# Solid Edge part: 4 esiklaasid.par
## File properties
Author: Henri
Template: Normal.par
Last saved by: Henri
Revision: 18
Application: Solid Edge
Accuracy: 0,990
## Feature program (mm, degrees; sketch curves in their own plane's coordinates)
sketch for "unnamed Protrusion 1" #1 plane through (178.0953, -250, 44.6428) normal (0.514496, 0, 0.857493) x-axis (0, 1, 0)
  line (-205, 61.7735) -> (-15, 61.7735)
  arc centre (-15, 51.7735) radius 10 from (-15, 61.7735) to (-5, 51.7735) cw
  line (-5, 51.7735) -> (-5, -51.7701)
  arc centre (-15, -51.7701) radius 10 from (-15, -61.7701) to (-5, -51.7701) ccw
  line (-15, -61.7701) -> (-205, -61.7701)
  arc centre (-205, -51.7701) radius 10 from (-215, -51.7701) to (-205, -61.7701) ccw
  line (-215, -51.7701) -> (-215, 51.7735)
  arc centre (-205, 51.7735) radius 10 from (-215, 51.7735) to (-205, 61.7735) cw
sketch for "unnamed Protrusion 1" #2 plane through (178.0953, -250, 44.6428) normal (0.514496, 0, 0.857493) x-axis (0, 1, 0)
  line (15, 61.7735) -> (205.778, 61.7735)
  arc centre (205.778, 52.5515) radius 9.222 from (215, 52.5515) to (205.778, 61.7735) ccw
  line (215, 52.5515) -> (215, -52.5481)
  arc centre (205.778, -52.5481) radius 9.222 from (205.778, -61.7701) to (215, -52.5481) ccw
  line (205.778, -61.7701) -> (15, -61.7701)
  arc centre (15, -51.7701) radius 10 from (5, -51.7701) to (15, -61.7701) ccw
  line (5, -51.7701) -> (5, 51.7735)
  arc centre (15, 51.7735) radius 10 from (5, 51.7735) to (15, 61.7735) cw
extrude "unnamed Protrusion 1" add finite 5 along -normal
sketch for "ExtrudedProtrusion_6" #1 plane through (178.0938, -360, 44.6437) normal (0.514496, 0, 0.857493) x-axis (0, 1, 0)
  line (-95, 64.2718) -> (95, 64.2718)
  arc centre (95, 51.7718) radius 12.5 from (95, 64.2718) to (107.5, 51.7718) cw
  line (107.5, 51.7718) -> (107.5, -51.7718)
  arc centre (95, -51.7718) radius 12.5 from (95, -64.2718) to (107.5, -51.7718) ccw
  line (95, -64.2718) -> (-95, -64.2718)
  arc centre (-95, -51.7718) radius 12.5 from (-107.5, -51.7718) to (-95, -64.2718) ccw
  line (-107.5, -51.7718) -> (-107.5, 51.7718)
  arc centre (-95, 51.7718) radius 12.5 from (-107.5, 51.7718) to (-95, 64.2718) cw
sketch for "ExtrudedProtrusion_6" #2 plane through (178.0938, -360, 44.6437) normal (0.514496, 0, 0.857493) x-axis (0, 1, 0)
  line (-95, 59.2718) -> (95, 59.2718)
  arc centre (95, 51.7718) radius 7.5 from (95, 59.2718) to (102.5, 51.7718) cw
  line (102.5, 51.7718) -> (102.5, -51.7718)
  arc centre (95, -51.7718) radius 7.5 from (95, -59.2718) to (102.5, -51.7718) ccw
  line (95, -59.2718) -> (-95, -59.2718)
  arc centre (-95, -51.7718) radius 7.5 from (-102.5, -51.7718) to (-95, -59.2718) ccw
  line (-102.5, -51.7718) -> (-102.5, 51.7718)
  arc centre (-95, 51.7718) radius 7.5 from (-102.5, 51.7718) to (-95, 59.2718) cw
sketch for "ExtrudedProtrusion_6" #3 plane through (178.0938, -360, 44.6437) normal (0.514496, 0, 0.857493) x-axis (0, 1, 0)
  line (125, 64.2718) -> (315.778, 64.2718)
  arc centre (315.778, 52.5498) radius 11.722 from (327.5, 52.5498) to (315.778, 64.2718) ccw
  line (327.5, 52.5498) -> (327.5, -52.5498)
  arc centre (315.778, -52.5498) radius 11.722 from (315.778, -64.2718) to (327.5, -52.5498) ccw
  line (315.778, -64.2718) -> (125, -64.2718)
  arc centre (125, -51.7718) radius 12.5 from (112.5, -51.7718) to (125, -64.2718) ccw
  line (112.5, -51.7718) -> (112.5, 51.7718)
  arc centre (125, 51.7718) radius 12.5 from (112.5, 51.7718) to (125, 64.2718) cw
sketch for "ExtrudedProtrusion_6" #4 plane through (178.0938, -360, 44.6437) normal (0.514496, 0, 0.857493) x-axis (0, 1, 0)
  line (125, 59.2718) -> (315.778, 59.2718)
  arc centre (315.778, 52.5498) radius 6.722 from (322.5, 52.5498) to (315.778, 59.2718) ccw
  line (322.5, 52.5498) -> (322.5, -52.5498)
  arc centre (315.778, -52.5498) radius 6.722 from (315.778, -59.2718) to (322.5, -52.5498) ccw
  line (315.778, -59.2718) -> (125, -59.2718)
  arc centre (125, -51.7718) radius 7.5 from (117.5, -51.7718) to (125, -59.2718) ccw
  line (117.5, -51.7718) -> (117.5, 51.7718)
  arc centre (125, 51.7718) radius 7.5 from (117.5, 51.7718) to (125, 59.2718) cw
extrude "ExtrudedProtrusion_6" add finite 2.5 along +normal
fillet "Round_20" radius 1
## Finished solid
Body 1: solid body, 88 faces, 208 edges, 128 vertices, 2 separate solids.
  Faces by surface: cylinder 40, plane 32, torus 16
  Edges by curve: line 112, circle 96
Bounding box of the edges (mm; curved faces can reach further): 111.568 x 435.000 x 70.908, from (122.5524, -467.5, 8.5749) to (234.1207, -32.5, 79.4831).
Cylindrical faces by radius (mm): R1 x16, R6.722 x2, R7.5 x6, R9.222 x2, R10 x6, R11.722 x2, R12.5 x6
Toroidal faces (ring radius, tube radius in mm): R7.722 r1 x2, R8.5 r1 x6, R10.722 r1 x2, R11.5 r1 x6
Planar faces by outward normal: +y 6, -y 6, oblique 20
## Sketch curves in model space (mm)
arc centre (133.6998, -265, 71.2801) radius 12.5 from (122.9811, -265, 77.7113) through (126.3442, -255.9078, 75.6935) to (133.6998, -252.5, 71.2801)
line (133.6998, -252.5, 71.2801) -> (222.4877, -252.5, 18.0074)
arc centre (222.4877, -265, 18.0074) radius 12.5 from (233.2064, -265, 11.5762) through (229.8433, -255.9078, 13.594) to (222.4877, -252.5, 18.0074)
line (233.2064, -265, 11.5762) -> (233.2064, -455, 11.5762)
arc centre (222.4877, -455, 18.0074) radius 12.5 from (222.4877, -467.5, 18.0074) through (230.2842, -463.578, 13.3295) to (233.2064, -455, 11.5762)
line (222.4877, -467.5, 18.0074) -> (133.6998, -467.5, 71.2801)
arc centre (133.6998, -455, 71.2801) radius 12.5 from (133.6998, -467.5, 71.2801) through (125.9033, -463.578, 75.958) to (122.9811, -455, 77.7113)
line (122.9811, -455, 77.7113) -> (122.9811, -265, 77.7113)
arc centre (133.6998, -265, 71.2801) radius 7.5 from (127.2686, -265, 75.1388) through (129.2865, -259.5447, 73.9281) to (133.6998, -257.5, 71.2801)
line (133.6998, -257.5, 71.2801) -> (222.4877, -257.5, 18.0074)
arc centre (222.4877, -265, 18.0074) radius 7.5 from (228.9189, -265, 14.1486) through (226.9011, -259.5447, 15.3593) to (222.4877, -257.5, 18.0074)
line (228.9189, -265, 14.1486) -> (228.9189, -455, 14.1486)
arc centre (222.4877, -455, 18.0074) radius 7.5 from (222.4877, -462.5, 18.0074) through (227.1656, -460.1468, 15.2006) to (228.9189, -455, 14.1486)
line (222.4877, -462.5, 18.0074) -> (133.6998, -462.5, 71.2801)
arc centre (133.6998, -455, 71.2801) radius 7.5 from (133.6998, -462.5, 71.2801) through (129.0219, -460.1468, 74.0868) to (127.2686, -455, 75.1388)
line (127.2686, -455, 75.1388) -> (127.2686, -265, 75.1388)
arc centre (133.6998, -235, 71.2801) radius 12.5 from (133.6998, -247.5, 71.2801) through (125.9033, -243.578, 75.958) to (122.9811, -235, 77.7113)
line (122.9811, -235, 77.7113) -> (122.9811, -44.222, 77.7113)
arc centre (133.0327, -44.222, 71.6804) radius 11.722 from (133.0327, -32.5, 71.6804) through (125.7215, -36.1779, 76.0671) to (122.9811, -44.222, 77.7113)
line (133.0327, -32.5, 71.6804) -> (223.1549, -32.5, 17.6071)
arc centre (223.1549, -44.222, 17.6071) radius 11.722 from (233.2064, -44.222, 11.5762) through (230.0527, -35.6957, 13.4684) to (223.1549, -32.5, 17.6071)
line (233.2064, -44.222, 11.5762) -> (233.2064, -235, 11.5762)
arc centre (222.4877, -235, 18.0074) radius 12.5 from (222.4877, -247.5, 18.0074) through (230.2842, -243.578, 13.3295) to (233.2064, -235, 11.5762)
line (222.4877, -247.5, 18.0074) -> (133.6998, -247.5, 71.2801)
arc centre (133.0327, -44.222, 71.6804) radius 6.722 from (133.0327, -37.5, 71.6804) through (128.84, -39.6091, 74.196) to (127.2686, -44.222, 75.1388)
line (133.0327, -37.5, 71.6804) -> (223.1549, -37.5, 17.6071)
arc centre (223.1549, -44.222, 17.6071) radius 6.722 from (228.9189, -44.222, 14.1486) through (227.1104, -39.3326, 15.2337) to (223.1549, -37.5, 17.6071)
line (228.9189, -44.222, 14.1486) -> (228.9189, -235, 14.1486)
arc centre (222.4877, -235, 18.0074) radius 7.5 from (222.4877, -242.5, 18.0074) through (227.1656, -240.1468, 15.2006) to (228.9189, -235, 14.1486)
line (222.4877, -242.5, 18.0074) -> (133.6998, -242.5, 71.2801)
arc centre (133.6998, -235, 71.2801) radius 7.5 from (133.6998, -242.5, 71.2801) through (129.0219, -240.1468, 74.0868) to (127.2686, -235, 75.1388)
line (127.2686, -235, 75.1388) -> (127.2686, -44.222, 75.1388)
arc centre (133.0327, -44.222, 71.6804) radius 9.222 from (133.0327, -35, 71.6804) through (127.2808, -37.8935, 75.1315) to (125.1249, -44.222, 76.4251)
line (133.0327, -35, 71.6804) -> (223.1549, -35, 17.6071)
arc centre (223.1549, -44.222, 17.6071) radius 9.222 from (231.0627, -44.222, 12.8624) through (228.5815, -37.5142, 14.3511) to (223.1549, -35, 17.6071)
line (231.0627, -44.222, 12.8624) -> (231.0627, -235, 12.8624)
arc centre (222.4877, -235, 18.0074) radius 10 from (222.4877, -245, 18.0074) through (228.7249, -241.8624, 14.265) to (231.0627, -235, 12.8624)
line (222.4877, -245, 18.0074) -> (133.6998, -245, 71.2801)
arc centre (133.6998, -235, 71.2801) radius 10 from (133.6998, -245, 71.2801) through (127.4626, -241.8624, 75.0224) to (125.1249, -235, 76.4251)
line (125.1249, -235, 76.4251) -> (125.1249, -44.222, 76.4251)
arc centre (133.6998, -265, 71.2801) radius 10 from (125.1249, -265, 76.4251) through (127.8153, -257.7263, 74.8108) to (133.6998, -255, 71.2801)
line (133.6998, -255, 71.2801) -> (222.4877, -255, 18.0074)
arc centre (222.4877, -265, 18.0074) radius 10 from (231.0627, -265, 12.8624) through (228.3722, -257.7263, 14.4767) to (222.4877, -255, 18.0074)
line (231.0627, -265, 12.8624) -> (231.0627, -455, 12.8624)
arc centre (222.4877, -455, 18.0074) radius 10 from (222.4877, -465, 18.0074) through (228.7249, -461.8624, 14.265) to (231.0627, -455, 12.8624)
line (222.4877, -465, 18.0074) -> (133.6998, -465, 71.2801)
arc centre (133.6998, -455, 71.2801) radius 10 from (133.6998, -465, 71.2801) through (127.4626, -461.8624, 75.0224) to (125.1249, -455, 76.4251)
line (125.1249, -455, 76.4251) -> (125.1249, -265, 76.4251)
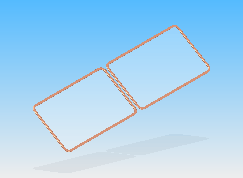
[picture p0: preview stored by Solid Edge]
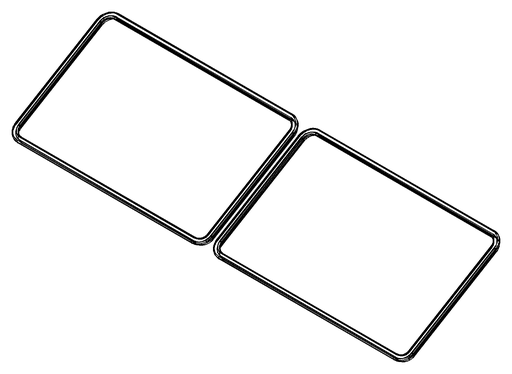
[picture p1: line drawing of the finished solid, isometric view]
